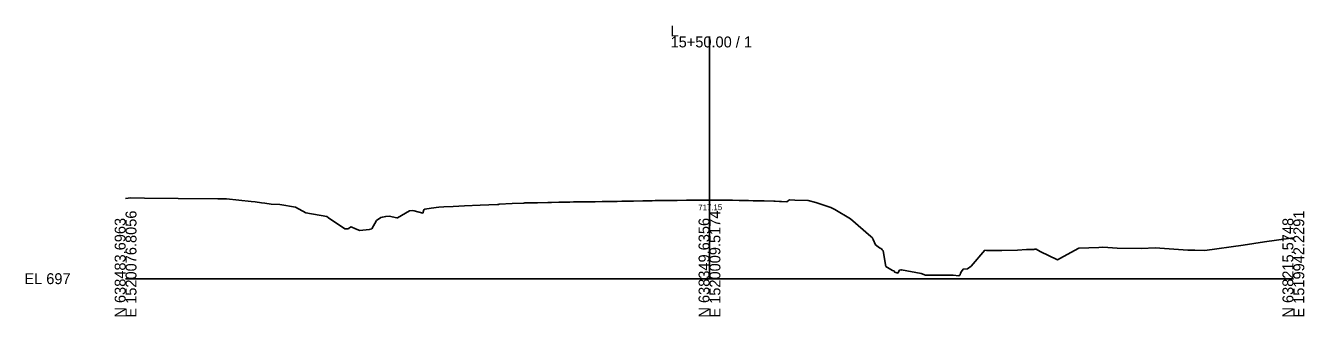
# Model space of a CAD drawing. Extents: x -26 to 3903, y -10 to 9531.
# Drawn here: x -25.7 to 302.8, y 5490.3 to 5565 of the extents above; entities that cross this region are included whole.
import ezdxf

# ---------------------------------------------------------------- set-up
doc = ezdxf.new("R2010")
doc.units = 0
for name, color, linetype in [('Default', 7, 'Continuous'), ('Exist Cross Section Cell', 7, 'Continuous'), ('Exist XS Center Line Elevation Label', 7, 'Continuous'), ('Exist XS Ground Line', 7, 'Continuous')]:
    doc.layers.add(name, color=color, linetype=linetype)

msp = doc.modelspace()

# ---------------------------------------------------------------- linework, layer by layer
at = {"layer": 'Exist Cross Section Cell'}
for p, q in [((150, 5500), (150, 5562.19)), ((0, 5500), (150, 5500)), ((150, 5500), (300, 5500))]:
    msp.add_line(p, q, dxfattribs=at)
at = {"layer": 'Exist XS Ground Line'}
msp.add_lwpolyline([(0, 5520.61), (1.39, 5520.73), (4.88, 5520.71), (13.53, 5520.62), (23.67, 5520.52), (25.93, 5520.47), (32.24, 5519.84), (33.31, 5519.71), (34.91, 5519.5), (35.74, 5519.41), (37.4, 5519.13), (39.6, 5519.02), (43.67, 5518.36), (46.34, 5516.87), (51.72, 5515.96), (52.17, 5515.63), (56.29, 5512.84), (56.97, 5512.82), (57.23, 5512.76), (57.36, 5512.93), (57.94, 5513.27), (59.09, 5512.83), (60.18, 5512.39), (62.6, 5512.6), (63.25, 5512.81), (64.42, 5514.9), (65.54, 5515.72), (65.98, 5515.82), (66.82, 5516), (67.68, 5516.04), (69.71, 5515.64), (69.87, 5515.65), (72.96, 5517.45), (73.6, 5517.51), (74.1, 5517.44), (76.32, 5516.85), (76.65, 5517.71), (76.91, 5517.84), (78.51, 5518.07), (80.48, 5518.32), (81.73, 5518.44), (84.18, 5518.56), (87.08, 5518.73), (91.06, 5518.89), (95.58, 5519.07), (95.76, 5519.08), (95.98, 5519.1), (99.28, 5519.27), (102.2, 5519.43), (102.37, 5519.43), (102.49, 5519.44), (103.76, 5519.46), (104.95, 5519.49), (105.15, 5519.49), (105.69, 5519.49), (105.82, 5519.49), (108.5, 5519.56), (109.45, 5519.58), (111.3, 5519.62), (111.36, 5519.62), (113.18, 5519.66), (114.09, 5519.68), (115.05, 5519.69), (116.89, 5519.73), (116.91, 5519.73), (116.94, 5519.73), (118.77, 5519.74), (119.69, 5519.76), (120.63, 5519.77), (122.47, 5519.79), (122.49, 5519.79), (122.51, 5519.79), (124.35, 5519.81), (125.26, 5519.82), (126.31, 5519.85), (127.49, 5519.88), (127.56, 5519.87), (127.65, 5519.87), (128.3, 5519.88), (129.21, 5519.89), (130.51, 5519.9), (132.9, 5519.95), (133.29, 5519.96), (133.42, 5519.96), (133.69, 5519.97), (135.29, 5520.01), (136.09, 5520.04), (138.5, 5520.08), (138.88, 5520.09), (139.25, 5520.09), (141.67, 5520.11), (144.09, 5520.14), (144.45, 5520.14), (144.81, 5520.14), (147.25, 5520.14), (148.71, 5520.15), (149.62, 5520.16), (149.79, 5520.16), (150.08, 5520.15), (150.37, 5520.15), (152.07, 5520.16), (152.87, 5520.16), (155.37, 5520.13), (155.66, 5520.12), (155.95, 5520.12), (157.61, 5520.09), (158.45, 5520.07), (159.56, 5520.06), (160.06, 5520.06), (161.19, 5520.03), (161.24, 5520.03), (161.53, 5520.02), (164.04, 5519.95), (166.55, 5519.87), (166.81, 5519.87), (166.88, 5519.86), (167.99, 5519.83), (168.07, 5519.83), (168.5, 5519.81), (169.89, 5519.74), (170.32, 5520.06), (170.56, 5520.23), (171.91, 5520.19), (175.39, 5520.11), (177.36, 5519.58), (181.19, 5518.3), (182.19, 5517.74), (186.22, 5515.34), (191.49, 5510.83), (191.88, 5510.46), (191.88, 5510.43), (191.89, 5510.36), (192.03, 5510.07), (192.69, 5508.71), (193.69, 5507.89), (194.18, 5507.7), (194.34, 5507.44), (194.64, 5507.19), (195.34, 5503.13), (196.98, 5502.13), (197.37, 5502.01), (197.59, 5501.68), (198.38, 5501.42), (198.8, 5502.21), (198.89, 5502.23), (199.16, 5502.22), (199.36, 5502.23), (204.35, 5501.33), (205.47, 5500.88), (212.61, 5500.86), (214.09, 5500.77), (214.37, 5501.01), (214.5, 5501.45), (214.72, 5501.8), (215.14, 5502.43), (216.32, 5502.55), (217.22, 5503.2), (220.77, 5507.31), (221.19, 5507.25), (222.43, 5507.21), (224.21, 5507.22), (225.11, 5507.21), (229.12, 5507.34), (231.45, 5507.48), (233.36, 5507.51), (233.61, 5507.61), (233.89, 5507.55), (234.94, 5506.94), (239.42, 5504.81), (240.95, 5505.71), (244.9, 5507.87), (250.04, 5508.02), (250.86, 5508.07), (252.34, 5508.02), (254.72, 5507.81), (260.98, 5507.78), (264.52, 5507.88), (272.91, 5507.29), (274.66, 5507.35), (277.26, 5507.27), (287.1, 5508.6), (292.58, 5509.46), (299.37, 5510.43), (300, 5510.49)], dxfattribs=at)

# ---------------------------------------------------------------- texts
at = {"layer": 'Default'}
msp.add_text('-', height=0.0001, dxfattribs=at).set_placement((0, 5500))
at = {"layer": 'Exist Cross Section Cell'}
for s, p in [('15+50.00 / 1', (140, 5559.39)), ('L', (140, 5562.19)), ('EL 697', (-26, 5498.6))]:
    msp.add_text(s, height=2.8, dxfattribs=at).set_placement(p)
for s, p in [('E 1520076.8056', (2.8, 5490)), ('E 1520009.5174', (152.8, 5490)), ('E 1519942.2291', (302.8, 5490)), ('N 638483.6963', (0, 5490)), ('N 638349.6356', (150, 5490)), ('N 638215.5748', (300, 5490))]:
    msp.add_text(s, height=2.8, rotation=90, dxfattribs=at).set_placement(p)
at = {"layer": 'Exist XS Center Line Elevation Label'}
msp.add_text('717.15', height=1.5, rotation=0.8401, dxfattribs=at).set_placement((147.14, 5517.52))

doc.saveas('drawing.dxf')
